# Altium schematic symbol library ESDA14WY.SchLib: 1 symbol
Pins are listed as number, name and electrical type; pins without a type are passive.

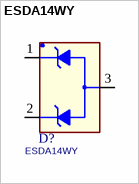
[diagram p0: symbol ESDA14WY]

## ESDA14WY
designator D?
footprint ST_SOT323-3L
pins: 1 K1, 2 K2, 3 A1A2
